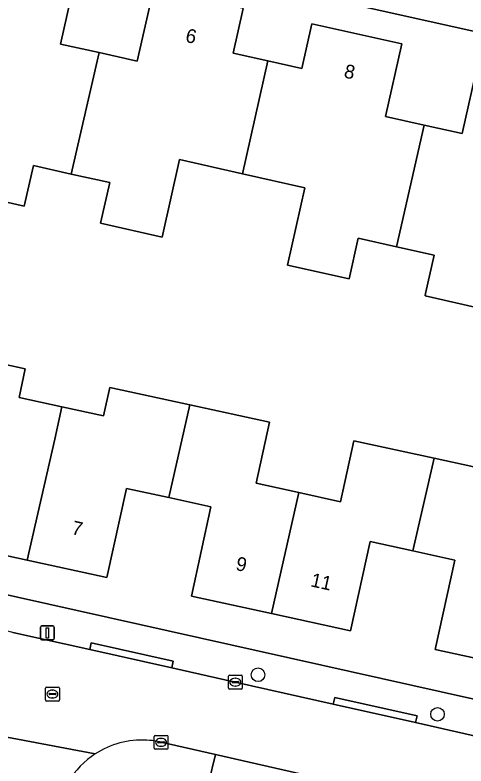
# Model space of a CAD drawing. Extents: x 161771 to 163125, y 382475 to 383179.
# Drawn here: x 162647.7 to 162680.2, y 382690.8 to 382745 of the extents above; entities that cross this region are included whole.
import ezdxf

# ---------------------------------------------------------------- set-up
doc = ezdxf.new("R2010")
doc.units = 0
for name, color, linetype in [('IMGEO_Boom', 7, 'Continuous'), ('IMGEO_Erf', 7, 'Continuous'), ('IMGEO_Kolk', 7, 'Continuous'), ('IMGEO_Lichtmast', 7, 'Continuous'), ('IMGEO_Pand', 7, 'Continuous'), ('IMGEO_Pand_nummerreeks', 7, 'Continuous'), ('IMGEO_Parkeervlak_open', 7, 'Continuous'), ('IMGEO_Rijbaan_lokaal_open', 7, 'Continuous'), ('IMGEO_Rioolput', 7, 'Continuous'), ('IMGEO_Voetpad_open', 7, 'Continuous')]:
    doc.layers.add(name, color=color, linetype=linetype)

msp = doc.modelspace()

# ---------------------------------------------------------------- linework, layer by layer
at = {"layer": 'IMGEO_Boom'}
for centre in [(162665.257, 382697.403), (162678.192, 382694.553)]:
    msp.add_circle(centre, 0.489, dxfattribs=at)
at = {"layer": 'IMGEO_Erf'}
for points in [[(162700.264, 382739.423), (162695.338, 382740.54), (162681.631, 382743.624), (162653.103, 382750)], [(162652.19, 382748.141), (162651.018, 382742.891), (162653.794, 382742.271), (162656.532, 382741.659), (162657.734, 382746.937)], [(162621.291, 382747.52), (162620.079, 382742.138), (162617.452, 382742.73), (162616.603, 382738.961), (162619.23, 382738.37), (162618.018, 382732.991), (162615.391, 382733.583), (162614.534, 382729.778), (162617.163, 382729.194), (162615.952, 382723.814), (162617.135, 382723.548), (162616.293, 382719.805), (162621.713, 382718.579), (162620.505, 382713.197), (162615.362, 382714.351), (162612.738, 382714.94), (162611.862, 382711.117), (162621.667, 382708.866), (162687.264, 382694.2), (162689.87, 382693.601)], [(162668.62, 382732.531), (162664.133, 382733.537), (162659.6, 382734.553), (162658.349, 382728.974), (162653.911, 382729.968), (162654.567, 382732.894), (162651.787, 382733.517), (162649.067, 382734.127), (162648.411, 382731.201), (162643.954, 382732.2), (162645.2, 382737.759), (162640.71, 382738.765), (162636.199, 382739.776), (162634.953, 382734.217), (162630.486, 382735.218), (162631.128, 382738.141), (162628.382, 382738.757), (162629.254, 382742.64), (162630.35, 382747.518)], [(162664.194, 382745.46), (162663.475, 382742.24), (162665.955, 382741.686), (162668.404, 382741.139), (162669.123, 382744.359), (162675.622, 382742.908), (162674.452, 382737.668), (162677.22, 382737.05), (162679.967, 382736.436), (162681.137, 382741.676), (162687.646, 382740.223), (162686.927, 382737.003), (162689.397, 382736.451), (162691.836, 382735.906), (162692.555, 382739.126), (162699.065, 382737.673), (162697.895, 382732.433), (162700.566, 382731.809), (162701.715, 382736.882)], [(162681.734, 382723.733), (162677.297, 382724.727), (162677.337, 382724.904), (162677.953, 382727.653), (162675.229, 382728.264), (162672.472, 382728.882), (162671.816, 382725.956), (162667.369, 382726.952), (162668.62, 382732.531)], [(162642.756, 382720.713), (162648.48, 382719.461), (162648.032, 382717.41), (162651.12, 382716.735), (162654.128, 382716.077), (162654.576, 382718.128), (162660.347, 382716.866), (162666.074, 382715.614), (162665.113, 382711.218), (162668.195, 382710.544), (162671.209, 382709.884), (162672.17, 382714.28), (162677.947, 382713.017), (162683.678, 382711.764)], [(162692.305, 382695.03), (162693.992, 382702.525), (162690.914, 382703.161), (162689.505, 382696.72), (162683.798, 382697.968), (162678.02, 382699.232), (162679.429, 382705.673), (162676.417, 382706.332), (162673.341, 382707.005), (162671.932, 382700.564), (162666.233, 382701.81), (162660.456, 382703.074), (162661.865, 382709.515), (162658.837, 382710.177), (162655.776, 382710.847), (162654.367, 382704.406), (162648.625, 382705.662), (162642.882, 382706.918)]]:
    msp.add_lwpolyline(points, dxfattribs=at)
at = {"layer": 'IMGEO_Kolk'}
for p, q in [((162663.122, 382696.445), (162663.122, 382697.297)), ((162663.197, 382697.371), (162664.049, 382697.371)), ((162663.61, 382697.151), (162663.635, 382697.151)), ((162664.123, 382697.297), (162664.123, 382696.445)), ((162663.381, 382696.865), (162663.381, 382696.877)), ((162663.819, 382696.828), (162663.421, 382696.828)), ((162663.424, 382696.914), (162663.822, 382696.914)), ((162663.633, 382696.591), (162663.608, 382696.591)), ((162663.865, 382696.877), (162663.865, 382696.865)), ((162664.049, 382696.371), (162663.197, 382696.371)), ((162657.765, 382692.103), (162657.765, 382692.955)), ((162657.84, 382693.029), (162658.692, 382693.029)), ((162658.253, 382692.809), (162658.278, 382692.809)), ((162658.766, 382692.955), (162658.766, 382692.103)), ((162658.024, 382692.523), (162658.024, 382692.535)), ((162658.462, 382692.486), (162658.064, 382692.486)), ((162658.067, 382692.572), (162658.465, 382692.572)), ((162658.276, 382692.249), (162658.251, 382692.249)), ((162658.508, 382692.535), (162658.508, 382692.523)), ((162658.692, 382692.029), (162657.84, 382692.029))]:
    msp.add_line(p, q, dxfattribs=at)
for points in [[(162663.122, 382696.445), (162663.122, 382697.297)], [(162663.197, 382697.371), (162664.049, 382697.371)], [(162664.123, 382697.297), (162664.123, 382696.445)], [(162664.049, 382696.371), (162663.197, 382696.371)], [(162657.765, 382692.103), (162657.765, 382692.955)], [(162657.84, 382693.029), (162658.692, 382693.029)], [(162658.766, 382692.955), (162658.766, 382692.103)], [(162658.692, 382692.029), (162657.84, 382692.029)]]:
    msp.add_lwpolyline(points, dxfattribs=at)
for centre, radius, start, end in [((162663.199, 382697.295), 0.0765, 91.552, 178.448), ((162663.199, 382697.295), 0.0765, 91.552, 178.448), ((162664.047, 382697.295), 0.0765, 1.552, 88.448), ((162664.047, 382697.295), 0.0765, 1.552, 88.448), ((162663.421, 382696.874), 0.0403, 85.8775, 175.7526), ((162663.418, 382696.864), 0.0366, 178.938, 274.7102), ((162663.822, 382696.871), 0.043, 264.8664, 352.4533), ((162663.826, 382696.876), 0.0386, 1.7309, 96.639), ((162663.199, 382696.447), 0.0765, 181.552, 268.448), ((162663.199, 382696.447), 0.0765, 181.552, 268.448), ((162664.047, 382696.447), 0.0765, 271.552, 358.448), ((162664.047, 382696.447), 0.0765, 271.552, 358.448), ((162657.842, 382692.953), 0.0765, 91.552, 178.448), ((162657.842, 382692.953), 0.0765, 91.552, 178.448), ((162658.69, 382692.953), 0.0765, 1.552, 88.448), ((162658.69, 382692.953), 0.0765, 1.552, 88.448), ((162658.064, 382692.532), 0.0403, 85.8775, 175.7526), ((162658.061, 382692.522), 0.0366, 178.938, 274.7102), ((162658.465, 382692.529), 0.043, 264.8664, 352.4533), ((162658.469, 382692.534), 0.0386, 1.7309, 96.639), ((162657.842, 382692.105), 0.0765, 181.552, 268.448), ((162657.842, 382692.105), 0.0765, 181.552, 268.448), ((162658.69, 382692.105), 0.0765, 271.552, 358.448), ((162658.69, 382692.105), 0.0765, 271.552, 358.448)]:
    msp.add_arc(centre, radius, start, end, dxfattribs=at)
for centre, major_axis, ratio, start_param, end_param in [((162663.609, 382696.871), (-0.387, 0.002), 0.722429, 4.712389, 7.853982), ((162663.634, 382696.871), (-0.39, 0.002), 0.717154, 1.570796, 4.712389), ((162658.252, 382692.529), (-0.387, 0.002), 0.722429, 4.712389, 7.853982), ((162658.277, 382692.529), (-0.39, 0.002), 0.717154, 1.570796, 4.712389)]:
    msp.add_ellipse(centre, major_axis=major_axis, ratio=ratio, start_param=start_param, end_param=end_param, dxfattribs=at)
at = {"layer": 'IMGEO_Lichtmast'}
for p, q in [((162649.674, 382700.924), (162650.464, 382700.924)), ((162650.464, 382700.924), (162649.674, 382700.924)), ((162649.574, 382700.024), (162649.574, 382700.824)), ((162649.574, 382700.824), (162649.574, 382700.024)), ((162650.564, 382700.824), (162650.564, 382700.024)), ((162650.564, 382700.024), (162650.564, 382700.824)), ((162650.464, 382699.924), (162649.674, 382699.924)), ((162649.674, 382699.924), (162650.464, 382699.924))]:
    msp.add_line(p, q, dxfattribs=at)
msp.add_lwpolyline([(162649.994, 382700.799), (162650.144, 382700.799), (162650.144, 382700.049), (162649.994, 382700.049), (162649.994, 382700.799)], dxfattribs=at)
for centre, start, end in [((162649.674, 382700.824), 90, 180), ((162649.674, 382700.824), 90, 180), ((162650.464, 382700.824), 0, 90), ((162650.464, 382700.824), 360, 90), ((162649.674, 382700.024), 180, 270), ((162649.674, 382700.024), 180, 270), ((162650.464, 382700.024), 270, 0), ((162650.464, 382700.024), 270, 0)]:
    msp.add_arc(centre, 0.1, start, end, dxfattribs=at)
at = {"layer": 'IMGEO_Pand'}
for points in [[(162651.787, 382733.517), (162653.794, 382742.271), (162651.018, 382742.891), (162652.19, 382748.141), (162645.747, 382749.645), (162644.98, 382746.37), (162642.534, 382746.916), (162640.71, 382738.765), (162645.2, 382737.759), (162643.954, 382732.2), (162648.411, 382731.201), (162649.067, 382734.127)], [(162664.133, 382733.537), (162665.955, 382741.686), (162663.475, 382742.24), (162664.194, 382745.46), (162657.734, 382746.937), (162656.532, 382741.659), (162653.794, 382742.271), (162651.787, 382733.517), (162654.567, 382732.894), (162653.911, 382729.968), (162658.349, 382728.974), (162659.6, 382734.553)], [(162675.229, 382728.264), (162677.22, 382737.05), (162674.452, 382737.668), (162675.622, 382742.908), (162669.123, 382744.359), (162668.404, 382741.139), (162665.955, 382741.686), (162664.133, 382733.537), (162668.62, 382732.531), (162667.369, 382726.952), (162671.816, 382725.956), (162672.472, 382728.882)], [(162689.397, 382736.451), (162686.927, 382737.003), (162687.646, 382740.223), (162681.137, 382741.676), (162679.967, 382736.436), (162677.22, 382737.05), (162675.229, 382728.264), (162677.953, 382727.653), (162677.337, 382724.904), (162677.297, 382724.727), (162681.734, 382723.733), (162682.98, 382729.292), (162687.519, 382728.275)], [(162641.246, 382714.025), (162644.291, 382713.359), (162642.882, 382706.918), (162648.625, 382705.662), (162650.6, 382714.4), (162651.12, 382716.735), (162648.032, 382717.41), (162648.48, 382719.461), (162642.756, 382720.713)], [(162660.347, 382716.866), (162654.576, 382718.128), (162654.128, 382716.077), (162651.12, 382716.735), (162650.6, 382714.4), (162648.625, 382705.662), (162654.367, 382704.406), (162655.776, 382710.847), (162658.837, 382710.177)], [(162660.347, 382716.866), (162658.837, 382710.177), (162661.865, 382709.515), (162660.456, 382703.074), (162666.233, 382701.81), (162668.195, 382710.544), (162665.113, 382711.218), (162666.074, 382715.614)], [(162668.195, 382710.544), (162666.233, 382701.81), (162671.932, 382700.564), (162673.341, 382707.005), (162676.417, 382706.332), (162677.947, 382713.017), (162672.17, 382714.28), (162671.209, 382709.884)], [(162685.768, 382706.701), (162682.717, 382707.368), (162683.678, 382711.764), (162677.947, 382713.017), (162676.417, 382706.332), (162679.429, 382705.673), (162678.02, 382699.232), (162683.798, 382697.968)]]:
    msp.add_lwpolyline(points, close=True, dxfattribs=at)
at = {"layer": 'IMGEO_Parkeervlak_open'}
msp.add_lwpolyline([(162662.182, 382691.642), (162661.694, 382689.582), (162679.221, 382685.624), (162679.677, 382687.683), (162675.174, 382688.698)], close=True, dxfattribs=at)
at = {"layer": 'IMGEO_Rijbaan_lokaal_open'}
for points in [[(162653.124, 382699.219), (162647.581, 382700.462), (162646.46, 382700.739), (162644.611, 382701.162), (162641.482, 382701.86), (162635.538, 382703.194), (162624.526, 382705.646), (162624.317, 382705.698), (162620.626, 382706.535), (162604.518, 382710.134), (162600.873, 382710.906), (162599.468, 382711.273)], [(162689.416, 382691.072), (162684.828, 382692.126), (162683.585, 382692.381), (162676.613, 382693.955), (162670.674, 382695.274), (162663.618, 382696.87), (162659.031, 382697.899), (162653.124, 382699.219)], [(162653.521, 382691.693), (162644.071, 382693.474)], [(162644.071, 382693.474), (162653.521, 382691.693)], [(162658.034, 382692.59), (162658.266, 382692.529), (162662.182, 382691.642), (162675.174, 382688.698), (162679.677, 382687.683), (162682.343, 382687.082), (162691.609, 382684.992), (162693.057, 382691.64)]]:
    msp.add_lwpolyline(points, dxfattribs=at)
for centre, radius, start, end in [((162656.9, 382686.494), 6.2, 86.8528, 123.0177), ((162656.88, 382686.31), 6.385, 79.5871, 86.7671), ((162656.905, 382686.485), 6.211, 123.0145, 148.7708)]:
    msp.add_arc(centre, radius, start, end, dxfattribs=at)
at = {"layer": 'IMGEO_Rioolput'}
for p, q in [((162649.933, 382695.584), (162649.933, 382696.436)), ((162650.008, 382696.51), (162650.86, 382696.51)), ((162650.192, 382696.004), (162650.192, 382696.016)), ((162650.235, 382696.053), (162650.633, 382696.053)), ((162650.421, 382696.29), (162650.446, 382696.29)), ((162650.676, 382696.016), (162650.676, 382696.004)), ((162650.934, 382696.436), (162650.934, 382695.584)), ((162650.86, 382695.51), (162650.008, 382695.51)), ((162650.63, 382695.967), (162650.232, 382695.967)), ((162650.444, 382695.73), (162650.419, 382695.73))]:
    msp.add_line(p, q, dxfattribs=at)
for points in [[(162649.933, 382695.584), (162649.933, 382696.436)], [(162650.008, 382696.51), (162650.86, 382696.51)], [(162650.934, 382696.436), (162650.934, 382695.584)], [(162650.86, 382695.51), (162650.008, 382695.51)]]:
    msp.add_lwpolyline(points, dxfattribs=at)
for centre, radius, start, end in [((162650.01, 382696.434), 0.0765, 91.552, 178.448), ((162650.01, 382696.434), 0.0765, 91.552, 178.448), ((162650.232, 382696.013), 0.0403, 85.8775, 175.7526), ((162650.229, 382696.003), 0.0366, 178.938, 274.7102), ((162650.633, 382696.01), 0.043, 264.8664, 352.4533), ((162650.637, 382696.015), 0.0386, 1.7309, 96.639), ((162650.858, 382696.434), 0.0765, 1.552, 88.448), ((162650.858, 382696.434), 0.0765, 1.552, 88.448), ((162650.01, 382695.586), 0.0765, 181.552, 268.448), ((162650.01, 382695.586), 0.0765, 181.552, 268.448), ((162650.858, 382695.586), 0.0765, 271.552, 358.448), ((162650.858, 382695.586), 0.0765, 271.552, 358.448)]:
    msp.add_arc(centre, radius, start, end, dxfattribs=at)
for centre, major_axis, ratio, start_param, end_param in [((162650.42, 382696.01), (-0.387, 0.002), 0.722429, 4.712389, 7.853982), ((162650.445, 382696.01), (-0.39, 0.002), 0.717154, 1.570796, 4.712389)]:
    msp.add_ellipse(centre, major_axis=major_axis, ratio=ratio, start_param=start_param, end_param=end_param, dxfattribs=at)
at = {"layer": 'IMGEO_Voetpad_open'}
for points in [[(162640.7, 382755.397), (162636.103, 382756.469), (162635.995, 382755.981), (162632.302, 382756.803), (162632.41, 382757.291), (162621.583, 382759.713), (162610.576, 382762.191), (162609.567, 382762.422), (162610.125, 382759.664), (162616.856, 382758.145), (162623.348, 382756.657), (162631.971, 382754.731), (162653.103, 382750), (162681.631, 382743.624), (162695.338, 382740.54), (162700.264, 382739.423)], [(162689.87, 382693.601), (162687.264, 382694.2), (162621.667, 382708.866)], [(162647.581, 382700.462), (162653.124, 382699.219), (162653.233, 382699.706), (162659.14, 382698.386), (162659.031, 382697.899), (162663.618, 382696.87), (162670.674, 382695.274), (162670.782, 382695.762), (162676.721, 382694.443), (162676.613, 382693.955), (162683.585, 382692.381), (162684.828, 382692.126), (162689.416, 382691.072)], [(162661.694, 382689.582), (162662.182, 382691.642), (162658.266, 382692.529), (162658.034, 382692.59)]]:
    msp.add_lwpolyline(points, dxfattribs=at)
for points in [[(162653.124, 382699.219), (162659.031, 382697.899), (162659.14, 382698.386), (162653.233, 382699.706)], [(162676.613, 382693.955), (162676.721, 382694.443), (162670.782, 382695.762), (162670.674, 382695.274)]]:
    msp.add_lwpolyline(points, close=True, dxfattribs=at)
for centre, radius, start, end in [((162656.9, 382686.494), 6.2, 86.8528, 123.0177), ((162656.88, 382686.31), 6.385, 79.5871, 86.7671), ((162656.905, 382686.485), 6.211, 123.0145, 148.7708)]:
    msp.add_arc(centre, radius, start, end, dxfattribs=at)

# ---------------------------------------------------------------- texts
at = {"layer": 'IMGEO_Pand_nummerreeks'}
for s, rotation, p in [('6', 347.1214, (162659.965, 382743.062)), ('8', 347.4143, (162671.394, 382740.491)), ('7', 347.6625, (162651.765, 382707.554)), ('9', 347.6627, (162663.595, 382704.967)), ('11', 347.6627, (162668.995, 382703.786))]:
    msp.add_text(s, height=1, rotation=rotation, dxfattribs=at).set_placement(p)

doc.saveas('drawing.dxf')
